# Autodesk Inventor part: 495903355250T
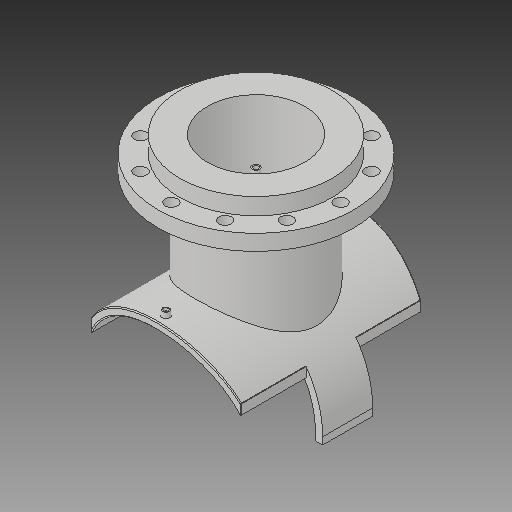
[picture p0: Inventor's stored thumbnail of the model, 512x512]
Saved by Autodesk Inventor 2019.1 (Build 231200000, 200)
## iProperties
Created: 2017-10
Part Number: 495903355250T
Material: Generic
Description: PLASSON FLANGED BRANCH SADDLE 315-355x250
Document SubType Name: Modeling
Designer: KIM
Mass: 2339.99 g
Surface Area: 3251.55 cm^2
Volume: 2339.99 cm^3
Density: 1 g/cm^3
Appearance: Default
Author: KIM
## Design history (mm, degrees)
derived "495904_495903.ipt"
feature "Solid1::495904_495903.ipt"
feature "Solid2::495904_495903.ipt"
tag "TaggingFeature1"
body "Solid1"
other parameters: "d0" = 355, "d1" = 15, "d2" = 315, "d4" = 0, "d6" = 105, "d7" = 0, "d12" = 203.1, "d13" = 14, "d14" = 189, "d16" = 5 deg, "d18" = 4, "d19" = 14, "d20" = 0, "d21" = 3, "d22" = 0, "d23" = 442.5, "d36" = 189, "d38" = 0, "d39" = 2, "d41" = 204, "d46" = 256, "d47" = 16, "d48" = 10.4, "d49" = 175, "d51" = 362.1, "d53" = 0, "d54" = 26, "d55" = 177.5, "d57" = 0, "d59" = 360 deg, "d61" = 33, "d63" = 0, "d67" = 15, "d68" = 125, "d70" = 0, "d71" = 2, "d_" = 355, "x_" = 15, "D_" = 16, "DN_" = 204, "t_" = 33, "s_" = 26, "Dp_" = 355
